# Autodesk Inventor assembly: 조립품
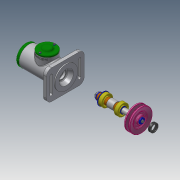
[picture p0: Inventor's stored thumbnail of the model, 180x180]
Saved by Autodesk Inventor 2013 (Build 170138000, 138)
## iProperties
Created: 2021-07
Part Number: 조립품
Document SubType Name: Assembly
Designer: user
Author: user
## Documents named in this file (20)
- C:\Users\user\Desktop\710706V1015\조립품.iam
- C:\Users\user\Desktop\710706V1015\본체.ipt
- C:\Users\user\Desktop\710706V1015\V-벨트풀리.ipt
- C:\Users\user\Desktop\710706V1015\너트 M10.ipt
- C:\Users\user\Desktop\710706V1015\멈춤링 15 x 1.ipt
- C:\Users\user\Desktop\710706V1015\멈춤링 35 x 1.6.ipt
- C:\Users\user\Desktop\710706V1015\베어링 15 x 35 x 11.ipt
- C:\Users\user\Desktop\710706V1015\볼트 M4 x 10.ipt
- C:\Users\user\Desktop\710706V1015\부시1.ipt
- C:\Users\user\Desktop\710706V1015\부시2.ipt
- C:\Users\user\Desktop\710706V1015\사이드 커버.ipt
- 사이드 커버.ipt
- C:\Users\user\Desktop\710706V1015\십자볼트 M3 x 10.ipt
- C:\Users\user\Desktop\710706V1015\오일 실 15 25 7.ipt
- C:\Users\user\Desktop\710706V1015\와셔 3 x 6.ipt
- C:\Users\user\Desktop\710706V1015\와셔 4 x 16.ipt
- C:\Users\user\Desktop\710706V1015\와셔 10 x 21.ipt
- C:\Users\user\Desktop\710706V1015\축.ipt
- C:\Users\user\Desktop\710706V1015\키 4 x 4 x 18.ipt
- C:\Users\user\Desktop\710706V1015\탑 커버.ipt
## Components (2 placed, 2 different names)
1. V-벨트풀리:1
2. ISO 4017 M4 x 10:1
